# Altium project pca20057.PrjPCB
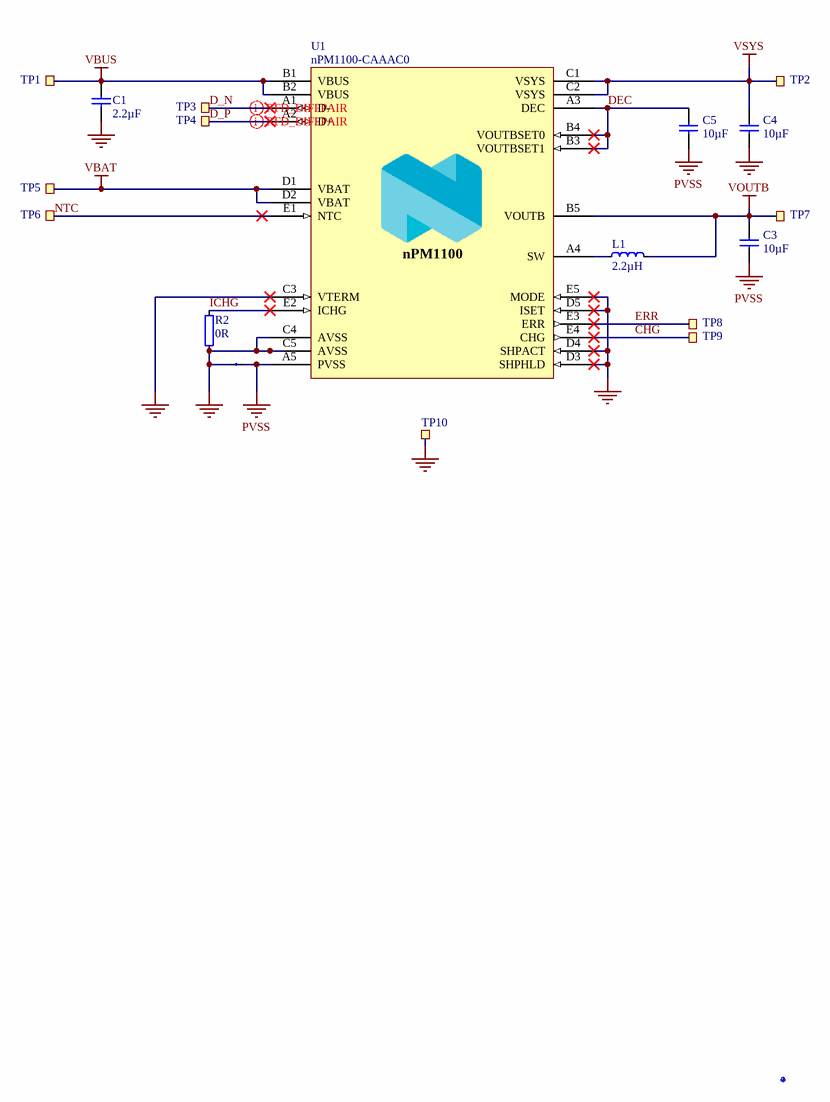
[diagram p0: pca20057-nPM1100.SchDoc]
Auth: GETR; BoardThickness: 1.6mm; BoardTitle: nPM1100 Reference Design Board; NrOfLayers: 2; Organization: Nordic Semiconductor; PCAName: PCA20057; PCBNumber: 400589; PCBRevision: 0166GETR; PCBStackup: 4001; ProjectName: nPM1100 Evaluation Kit; ProjectNumber: 4477; Rev: 1.0.0; SilkscreenColor: White; SoldermaskColor: Blue; SurfaceFinish: ENIG Gold
1 sheet, 19 parts. Net scope: global (net labels, ports and power ports of the same name join across sheets).
Board file: 400589.PcbDoc

## Sheet pca20057-nPM1100.SchDoc: PCA20057 - nPM1100
size A3; Organization: Nordic Semiconductor; DocumentNumber: 1; Revision: 1.0.0; SheetNumber: 1; SheetTotal: 1; Author: GETR; CompanyName: Nordic Semiconductor; DocumentSize: A4; Project Number: 4477

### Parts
C1  2.2µF  [CAPC1608X06L]
C3  10µF  [CAPC1608X06L]
C4  10µF  [CAPC1608X06L]
C5  10µF  [CAPC1608X06L]
Fid1  Fiducial mark  [Fiducial]  (value not drawn)
J1  N.A.  [2 PIN STARPOINT]  (value not drawn)  (net tie, no BOM)
L1  2.2µH  [INDC1608X06L]
R2  0R  [RESC0603X03L_C]
TP1  TP  [TESTPAD-TH - 0.5mm]  (value not drawn)  (no BOM)
TP2  TP  [TESTPAD-TH - 0.5mm]  (value not drawn)  (no BOM)
TP3  TP  [TESTPAD-TH - 0.5mm]  (value not drawn)  (no BOM)
TP4  TP  [TESTPAD-TH - 0.5mm]  (value not drawn)  (no BOM)
TP5  TP  [TESTPAD-TH - 0.5mm]  (value not drawn)  (no BOM)
TP6  TP  [TESTPAD-TH - 0.5mm]  (value not drawn)  (no BOM)
TP7  TP  [TESTPAD-TH - 0.5mm]  (value not drawn)  (no BOM)
TP8  TP  [TESTPAD-TH - 0.5mm]  (value not drawn)  (no BOM)
TP9  TP  [TESTPAD-TH - 0.5mm]  (value not drawn)  (no BOM)
TP10  TP  [TESTPAD-TH - 0.5mm]  (value not drawn)  (no BOM)
U1  nPM1100-CAAAC0  [BGA25C40P5X5_200X200X50]

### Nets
GND: C1.1 C4.1 J1.2 R2.1 TP10.1 U1.C3(VTERM) U1.C4(AVSS) U1.C5(AVSS) U1.D3(SHPHLD) U1.D4(SHPACT) U1.D5(ISET) U1.E5(MODE)
PVSS: C3.1 C5.1 J1.1 U1.A5(PVSS)
VBAT: TP5.1 U1.D1(VBAT) U1.D2(VBAT)
VBUS: C1.2 TP1.1 U1.B1(VBUS) U1.B2(VBUS)
VOUTB: C3.2 L1.2 TP7.1 U1.B5(VOUTB)
VSYS: C4.2 TP2.1 U1.C1(VSYS) U1.C2(VSYS)
CHG: TP9.1 U1.E4(CHG)
D_N: TP3.1 U1.A1(D-)
D_P: TP4.1 U1.A2(D+)
DEC: C5.2 U1.A3(DEC) U1.B3(VOUTBSET1) U1.B4(VOUTBSET0)
ERR: TP8.1 U1.E3(ERR)
ICHG: R2.2 U1.E2(ICHG)
NTC: TP6.1 U1.E1(NTC)
NetL1_1: L1.1 U1.A4(SW)

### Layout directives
differential pair; differential pair class USB: D_N, D_P

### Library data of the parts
C1 = C0603-2µ2-25V-X5R: Capacitor, Ceramic, X5R, ±10%, 25V; Manufacturer: Murata; Manufacturer Part Number: GRM188R61E225KA12D; Pad Count: 2; Artikkelnr Noca: N.A.
C3-C5 = 0603-10u-10V-X7T-GRM188: CAP CER 10UF 10V X7T 0603; Manufacturer: Murata; Manufacturer Part Number: GRM188D71A106MA73; Part number IPS: 00000004696; Note: 10VDC; Artikkelnr Noca: N.A.; Pad Count: 2
Fid1 = Fid-Mark: Artikkelnr Noca: N.A.; Pad Count: 1
J1 = 2 pin starpoint: Starpoint; Pad Count: 2
L1 = BRL1608T2R2M: FIXED IND 2.2UH 500MA 520 MOHM; Manufacturer: Taiyo Yuden; Pad Count: 2; Note: -40°C ~ 105°C; Artikkelnr Noca: N.A.
R2 = R0201-0R: Resistor, ±5%, 0.05W; Manufacturer: N.A.; Part number IPS: 00000003245; Pad Count: 2; Note: Chip Res 5%
TP1-TP10 = Testpoint TH 0.5mm: Testpoint, through hole; Manufacturer: N.A.; Pad Count: 1
U1 = nPM1100-CAAAC0: Li-Ion/Li-Polymer USB battery charger with a high efficiency buck regulator; Manufacturer: Nordic Semiconductor; Note: N.A.; Pad Count: 25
